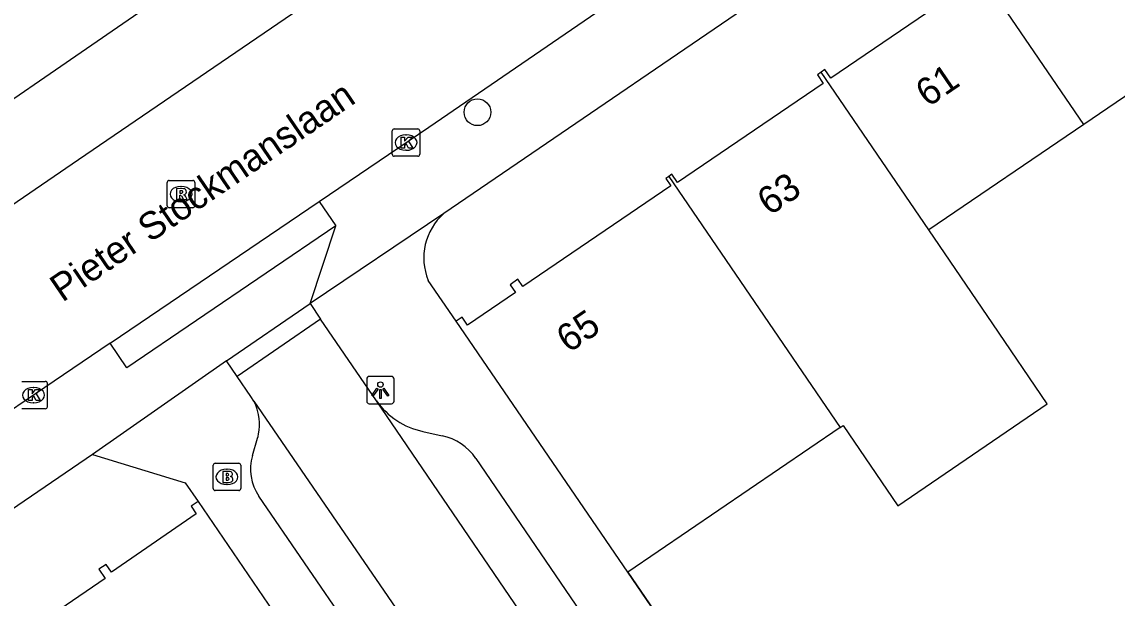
# Model space of a CAD drawing. Extents: x 157466 to 158888, y 383063 to 384677.
# Drawn here: x 158091.88 to 158131.78, y 383890.66 to 383911.68 of the extents above; entities that cross this region are included whole.
import ezdxf

# ---------------------------------------------------------------- set-up
doc = ezdxf.new("R2010")
doc.units = 0
for name, color, linetype in [('IMGEO_Boom', 7, 'Continuous'), ('IMGEO_Brandkraan', 7, 'Continuous'), ('IMGEO_Fietspad_gesloten', 7, 'Continuous'), ('IMGEO_Kolk', 7, 'Continuous'), ('IMGEO_Lichtpunt', 7, 'Continuous'), ('IMGEO_Muur', 7, 'Continuous'), ('IMGEO_Openbare_ruimte_label', 7, 'Continuous'), ('IMGEO_Pand', 7, 'Continuous'), ('IMGEO_Pand_nummerreeks', 7, 'Continuous'), ('IMGEO_Rijbaan_lokaal_open', 7, 'Continuous'), ('IMGEO_Rioolput', 7, 'Continuous'), ('IMGEO_Voetpad_open', 7, 'Continuous')]:
    doc.layers.add(name, color=color, linetype=linetype)

msp = doc.modelspace()

# ---------------------------------------------------------------- linework, layer by layer
at = {"layer": 'IMGEO_Boom'}
msp.add_circle((158108.477, 383908.389), 0.489, dxfattribs=at)
at = {"layer": 'IMGEO_Brandkraan'}
for p, q in [((158098.849, 383894.661), (158098.849, 383895.513)), ((158098.924, 383895.587), (158099.776, 383895.587)), ((158099.85, 383895.513), (158099.85, 383894.661)), ((158099.337, 383895.367), (158099.362, 383895.367)), ((158099.36, 383894.807), (158099.335, 383894.807)), ((158099.776, 383894.587), (158098.924, 383894.587))]:
    msp.add_line(p, q, dxfattribs=at)
for points in [[(158098.849, 383894.661), (158098.849, 383895.513)], [(158098.924, 383895.587), (158099.776, 383895.587)], [(158099.85, 383895.513), (158099.85, 383894.661)], [(158099.197, 383895.287), (158099.197, 383894.887), (158099.41, 383894.887)], [(158099.428, 383895.287), (158099.197, 383895.287)], [(158099.376, 383895.206), (158099.322, 383895.206), (158099.322, 383895.13)], [(158099.322, 383895.13), (158099.375, 383895.13)], [(158099.384, 383895.054), (158099.322, 383895.054), (158099.322, 383894.973)], [(158099.322, 383894.973), (158099.384, 383894.973)], [(158099.776, 383894.587), (158098.924, 383894.587)]]:
    msp.add_lwpolyline(points, dxfattribs=at)
for centre, radius, start, end in [((158098.926, 383895.511), 0.0765, 91.552, 178.448), ((158098.926, 383895.511), 0.0765, 91.552, 178.448), ((158099.774, 383895.511), 0.0765, 1.552, 88.448), ((158099.774, 383895.511), 0.0765, 1.552, 88.448), ((158099.377, 383895.168), 0.0379, 267.8285, 90.9355), ((158099.432, 383895.142), 0.145, 59.4692, 91.5367), ((158099.457, 383895.189), 0.0922, 285.5137, 58.1501), ((158099.462, 383894.997), 0.105, 301.3115, 78.989), ((158098.926, 383894.663), 0.0765, 181.552, 268.448), ((158098.926, 383894.663), 0.0765, 181.552, 268.448), ((158099.385, 383895.013), 0.0404, 269.8759, 90.5077), ((158099.416, 383895.138), 0.251, 268.6676, 293.5347), ((158099.774, 383894.663), 0.0765, 271.552, 358.448), ((158099.774, 383894.663), 0.0765, 271.552, 358.448)]:
    msp.add_arc(centre, radius, start, end, dxfattribs=at)
for centre, major_axis, ratio, start_param, end_param in [((158099.336, 383895.087), (-0.387, 0.002), 0.722429, 4.712389, 7.853982), ((158099.361, 383895.087), (-0.39, 0.002), 0.717154, 1.570796, 4.712389)]:
    msp.add_ellipse(centre, major_axis=major_axis, ratio=ratio, start_param=start_param, end_param=end_param, dxfattribs=at)
at = {"layer": 'IMGEO_Fietspad_gesloten'}
msp.add_lwpolyline([(158045.888, 383877.777), (158060.694, 383887.801), (158072.982, 383896.204), (158086.084, 383905.105), (158098.205, 383913.461), (158107.782, 383920.254), (158110.203, 383922.414), (158112.062, 383924.982)], dxfattribs=at)
at = {"layer": 'IMGEO_Kolk'}
for p, q in [((158105.372, 383906.855), (158105.372, 383907.707)), ((158105.447, 383907.781), (158106.299, 383907.781)), ((158105.86, 383907.561), (158105.885, 383907.561)), ((158106.373, 383907.707), (158106.373, 383906.855)), ((158106.299, 383906.781), (158105.447, 383906.781)), ((158105.883, 383907.001), (158105.858, 383907.001)), ((158091.878, 383898.57), (158092.73, 383898.57)), ((158092.291, 383898.35), (158092.316, 383898.35)), ((158092.804, 383898.496), (158092.804, 383897.644)), ((158092.73, 383897.57), (158091.878, 383897.57)), ((158092.314, 383897.79), (158092.289, 383897.79))]:
    msp.add_line(p, q, dxfattribs=at)
for points in [[(158105.372, 383906.855), (158105.372, 383907.707)], [(158105.447, 383907.781), (158106.299, 383907.781)], [(158105.693, 383907.481), (158105.816, 383907.481), (158105.816, 383907.33), (158105.946, 383907.481), (158106.11, 383907.481), (158105.964, 383907.33), (158106.117, 383907.081), (158105.965, 383907.081), (158105.88, 383907.245), (158105.816, 383907.178), (158105.816, 383907.081), (158105.693, 383907.081), (158105.693, 383907.481)], [(158106.373, 383907.707), (158106.373, 383906.855)], [(158106.299, 383906.781), (158105.447, 383906.781)], [(158091.878, 383898.57), (158092.73, 383898.57)], [(158092.124, 383898.27), (158092.247, 383898.27), (158092.247, 383898.119), (158092.377, 383898.27), (158092.541, 383898.27), (158092.395, 383898.119), (158092.548, 383897.87), (158092.396, 383897.87), (158092.311, 383898.034), (158092.247, 383897.967), (158092.247, 383897.87), (158092.124, 383897.87), (158092.124, 383898.27)], [(158092.804, 383898.496), (158092.804, 383897.644)], [(158092.73, 383897.57), (158091.878, 383897.57)]]:
    msp.add_lwpolyline(points, dxfattribs=at)
for centre, start, end in [((158105.449, 383907.705), 91.552, 178.448), ((158105.449, 383907.705), 91.552, 178.448), ((158106.297, 383907.705), 1.552, 88.448), ((158106.297, 383907.705), 1.552, 88.448), ((158105.449, 383906.857), 181.552, 268.448), ((158105.449, 383906.857), 181.552, 268.448), ((158106.297, 383906.857), 271.552, 358.448), ((158106.297, 383906.857), 271.552, 358.448), ((158092.728, 383898.494), 1.552, 88.448), ((158092.728, 383898.494), 1.552, 88.448), ((158092.728, 383897.646), 271.552, 358.448), ((158092.728, 383897.646), 271.552, 358.448)]:
    msp.add_arc(centre, 0.0765, start, end, dxfattribs=at)
for centre, major_axis, ratio, start_param, end_param in [((158105.859, 383907.281), (-0.387, 0.002), 0.722429, 4.712389, 7.853982), ((158105.884, 383907.281), (-0.39, 0.002), 0.717154, 1.570796, 4.712389), ((158092.29, 383898.07), (-0.387, 0.002), 0.722429, 4.712389, 7.853982), ((158092.315, 383898.07), (-0.39, 0.002), 0.717154, 1.570796, 4.712389)]:
    msp.add_ellipse(centre, major_axis=major_axis, ratio=ratio, start_param=start_param, end_param=end_param, dxfattribs=at)
at = {"layer": 'IMGEO_Lichtpunt'}
for p, q in [((158104.441, 383898.656), (158104.441, 383897.849)), ((158104.441, 383898.656), (158104.441, 383897.849)), ((158105.343, 383898.751), (158104.535, 383898.751)), ((158105.343, 383898.751), (158104.535, 383898.751)), ((158105.437, 383897.849), (158105.437, 383898.656)), ((158105.437, 383897.849), (158105.437, 383898.656)), ((158104.535, 383897.755), (158105.343, 383897.755)), ((158104.535, 383897.755), (158105.343, 383897.755))]:
    msp.add_line(p, q, dxfattribs=at)
for points in [[(158104.815, 383898.32), (158104.854, 383898.292), (158104.666, 383898.03), (158104.628, 383898.057), (158104.815, 383898.32)], [(158104.917, 383898.272), (158104.964, 383898.272), (158104.964, 383897.95), (158104.917, 383897.95), (158104.917, 383898.272)], [(158105.027, 383898.292), (158105.065, 383898.319), (158105.252, 383898.057), (158105.213, 383898.029), (158105.027, 383898.292)]]:
    msp.add_lwpolyline(points, dxfattribs=at)
msp.add_circle((158104.94, 383898.454), 0.0994, dxfattribs=at)
for centre, start, end in [((158104.535, 383898.656), 90, 180), ((158104.535, 383898.656), 90, 180), ((158105.343, 383898.656), 0, 90), ((158105.343, 383898.656), 0, 90), ((158104.535, 383897.849), 180, 270), ((158104.535, 383897.849), 180, 270), ((158105.343, 383897.849), 270, 0), ((158105.343, 383897.849), 270, 360)]:
    msp.add_arc(centre, 0.0946, start, end, dxfattribs=at)
at = {"layer": 'IMGEO_Muur'}
msp.add_lwpolyline([(158113.955, 383891.614), (158120.452, 383882.107)], dxfattribs=at)
at = {"layer": 'IMGEO_Pand'}
for points in [[(158126.638, 383913.71), (158126.513, 383913.625), (158126.731, 383913.306), (158121.347, 383909.636), (158121.137, 383909.944), (158120.998, 383909.849)], [(158130.566, 383907.942), (158126.638, 383913.71)], [(158136.155, 383911.752), (158130.566, 383907.942)], [(158120.998, 383909.849), (158120.861, 383909.756), (158121.077, 383909.439), (158115.767, 383905.82), (158115.56, 383906.123), (158115.45, 383906.048)], [(158124.919, 383904.093), (158120.998, 383909.849)], [(158130.566, 383907.942), (158124.919, 383904.093)], [(158115.45, 383906.048), (158115.34, 383905.972), (158115.52, 383905.709), (158110.128, 383902.034), (158109.951, 383902.294), (158109.665, 383902.098), (158109.862, 383901.809), (158108.119, 383900.62), (158107.921, 383900.91), (158107.704, 383900.761)], [(158115.45, 383906.048), (158121.691, 383896.886)], [(158121.691, 383896.886), (158121.798, 383896.959), (158123.789, 383894.037), (158129.239, 383897.751), (158127.249, 383900.673), (158124.919, 383904.093)], [(158113.955, 383891.614), (158107.704, 383900.761)], [(158121.691, 383896.886), (158113.955, 383891.614)], [(158098.294, 383894.19), (158098.039, 383894.016), (158098.231, 383893.736), (158095.139, 383891.616), (158094.946, 383891.896), (158094.683, 383891.717), (158094.916, 383891.375), (158089.478, 383887.675), (158089.249, 383888.012), (158089.11, 383887.918)], [(158098.294, 383894.19), (158101.036, 383890.178)]]:
    msp.add_lwpolyline(points, dxfattribs=at)
at = {"layer": 'IMGEO_Rijbaan_lokaal_open'}
for points in [[(158102.711, 383905.136), (158106.703, 383907.846), (158135.426, 383927.536)], [(158088.566, 383902.987), (158093.943, 383906.66), (158103.038, 383912.884)], [(158095.088, 383899.962), (158102.711, 383905.136)], [(158102.753, 383900.843), (158099.723, 383898.748)], [(158104.792, 383897.863), (158102.753, 383900.843)], [(158095.088, 383899.962), (158088.313, 383895.363), (158082.388, 383891.324)], [(158100.324, 383897.852), (158100.223, 383898.017), (158099.723, 383898.748)], [(158100.324, 383897.852), (158111.949, 383880.885)], [(158116.359, 383880.881), (158104.792, 383897.863)]]:
    msp.add_lwpolyline(points, dxfattribs=at)
at = {"layer": 'IMGEO_Rioolput'}
for p, q in [((158097.249, 383905.902), (158098.101, 383905.902)), ((158097.174, 383904.976), (158097.174, 383905.828)), ((158097.662, 383905.682), (158097.687, 383905.682)), ((158098.175, 383905.828), (158098.175, 383904.976)), ((158097.685, 383905.122), (158097.66, 383905.122)), ((158098.101, 383904.902), (158097.249, 383904.902))]:
    msp.add_line(p, q, dxfattribs=at)
for points in [[(158097.249, 383905.902), (158098.101, 383905.902)], [(158097.174, 383904.976), (158097.174, 383905.828)], [(158097.763, 383905.6), (158097.511, 383905.602), (158097.511, 383905.202)], [(158097.689, 383905.521), (158097.635, 383905.521), (158097.635, 383905.44)], [(158097.635, 383905.44), (158097.687, 383905.44)], [(158098.175, 383905.828), (158098.175, 383904.976)], [(158097.511, 383905.202), (158097.635, 383905.202), (158097.635, 383905.364), (158097.646, 383905.364)], [(158097.693, 383905.335), (158097.764, 383905.202), (158097.904, 383905.202), (158097.839, 383905.328)], [(158098.101, 383904.902), (158097.249, 383904.902)]]:
    msp.add_lwpolyline(points, dxfattribs=at)
for centre, radius, start, end in [((158097.251, 383905.826), 0.0765, 91.552, 178.448), ((158097.251, 383905.826), 0.0765, 91.552, 178.448), ((158098.099, 383905.826), 0.0765, 1.552, 88.448), ((158098.099, 383905.826), 0.0765, 1.552, 88.448), ((158097.671, 383905.629), 0.19, 274.7715, 282.9687), ((158097.695, 383905.425), 0.0964, 77.0061, 93.1865), ((158097.709, 383905.482), 0.0378, 276.6634, 79.6772), ((158097.762, 383905.49), 0.109, 350.3612, 89.416), ((158097.76, 383905.49), 0.112, 277.5842, 350.9817), ((158097.645, 383905.311), 0.0533, 26.0293, 88.6989), ((158097.744, 383905.275), 0.108, 29.5134, 73.7905), ((158097.251, 383904.978), 0.0765, 181.552, 268.448), ((158097.251, 383904.978), 0.0765, 181.552, 268.448), ((158098.099, 383904.978), 0.0765, 271.552, 358.448), ((158098.099, 383904.978), 0.0765, 271.552, 358.448)]:
    msp.add_arc(centre, radius, start, end, dxfattribs=at)
for centre, major_axis, ratio, start_param, end_param in [((158097.661, 383905.402), (-0.387, 0.002), 0.722429, 4.712389, 7.853982), ((158097.686, 383905.402), (-0.39, 0.002), 0.717154, 1.570796, 4.712389)]:
    msp.add_ellipse(centre, major_axis=major_axis, ratio=ratio, start_param=start_param, end_param=end_param, dxfattribs=at)
at = {"layer": 'IMGEO_Voetpad_open'}
for points in [[(158151.882, 383932.744), (158148.818, 383933.08), (158107.25, 383904.692)], [(158102.711, 383905.136), (158103.318, 383904.242)], [(158107.25, 383904.692), (158102.377, 383901.408)], [(158103.318, 383904.242), (158095.695, 383899.068), (158095.088, 383899.962)], [(158102.377, 383901.408), (158103.318, 383904.242)], [(158107.704, 383900.761), (158106.683, 383902.256)], [(158099.331, 383899.321), (158102.377, 383901.408)], [(158102.377, 383901.408), (158102.753, 383900.843)], [(158099.331, 383899.321), (158094.454, 383895.908)], [(158099.723, 383898.748), (158099.331, 383899.321)], [(158100.277, 383895.865), (158100.462, 383896.496), (158100.483, 383896.564), (158100.503, 383896.657), (158100.524, 383896.793), (158100.535, 383896.941), (158100.535, 383897.087), (158100.528, 383897.206), (158100.502, 383897.362), (158100.452, 383897.555), (158100.404, 383897.699), (158100.324, 383897.852)], [(158106.486, 383896.742), (158107.189, 383896.59)], [(158094.454, 383895.908), (158061.486, 383873.374), (158052.925, 383867.553), (158052.526, 383864.224)], [(158094.454, 383895.908), (158097.831, 383894.867), (158098.294, 383894.19)], [(158108.418, 383895.762), (158116.388, 383884.061), (158116.502, 383883.566), (158116.211, 383881.567)], [(158108.834, 383882.224), (158100.512, 383894.383)], [(158120.445, 383882.102), (158113.955, 383891.614)]]:
    msp.add_lwpolyline(points, dxfattribs=at)
for centre, radius, start, end in [((158108.671, 383903.077), 2.151, 131.3427, 202.4517), ((158107.084, 383899.486), 2.808, 215.3002, 257.7108), ((158106.765, 383894.635), 2, 34.2911, 77.7712), ((158101.949, 383895.371), 1.744, 163.5255, 214.4952)]:
    msp.add_arc(centre, radius, start, end, dxfattribs=at)

# ---------------------------------------------------------------- texts
at = {"layer": 'IMGEO_Openbare_ruimte_label'}
msp.add_text('Pieter Stockmanslaan', height=1, rotation=34.2783, dxfattribs=at).set_placement((158093.352, 383901.437))
at = {"layer": 'IMGEO_Pand_nummerreeks'}
for s, rotation, p in [('61', 34.2806, (158124.887, 383908.549)), ('63', 34.2801, (158119.116, 383904.589)), ('65', 34.2806, (158111.798, 383899.583))]:
    msp.add_text(s, height=1, rotation=rotation, dxfattribs=at).set_placement(p)

doc.saveas('drawing.dxf')
